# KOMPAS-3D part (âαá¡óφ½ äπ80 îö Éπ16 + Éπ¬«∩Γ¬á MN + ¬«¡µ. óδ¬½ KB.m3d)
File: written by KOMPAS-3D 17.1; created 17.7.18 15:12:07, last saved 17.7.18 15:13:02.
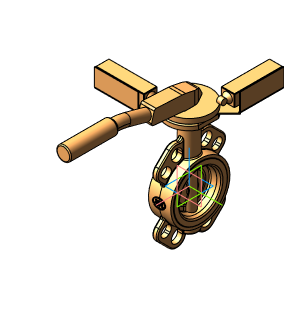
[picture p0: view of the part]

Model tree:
1. Операция без истории:2  (labels: Сталь 20  ГОСТ 1050-2013)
